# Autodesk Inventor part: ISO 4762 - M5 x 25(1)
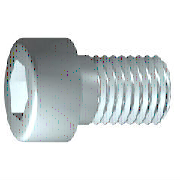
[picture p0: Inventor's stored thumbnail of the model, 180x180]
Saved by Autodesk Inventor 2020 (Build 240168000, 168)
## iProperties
Created: 2019-01
Part Number: ISO 4762 - M5 x 25(1)
Material: Nerezová ocel 440C
Description: Šroub s válcovou hlavou s vnitřním šestihranem
Document SubType Name: Modeling
Standard: ISO 4762
Designer: doma
Standard Revision: Fourth edition 2004-03-01
Standards Organization: ISO
Language: cs-CZ
Size Designation: M5 x 25
Categories: <MemberInstance><Categories><Category DisplayName="Spojovací materiál" InternalName="e4da775c-781d-43d5-af7c-5136215cf5a6" Mnemonic="FSTN"><Category DisplayName
Density: 7.75 g/cm^3
Appearance: Pololeštěná
IsCustomPart: 0
Author: doma
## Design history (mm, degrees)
sketch "Náčrt1"
  geometry: L1 (-1.167, 0)-(25, 0); L2 (25, 0)-(25, 2.5); L3 (25, 2.5)-(2, 2.5); L4 (2, 2.5)-(1.509, 2.5); L5 (1.509, 2.5)-(0, 2.5); L6 (0, 2.5)-(0, 4.25); L7 (0, 4.25)-(-5, 4.25); L8 (-5, 4.25)-(-5, 2.309); L9 (-5, 2.309)-(-2.5, 2.309); L10 (-2.5, 2.309)-(-1.167, 0); L11 (-11, 0)-(31, 0) reference; L12 (0, -0.85)-(0, 5.1) reference; L13 (2, 2.5)-(0, 2.5)
  constraints: 22 end point, 6 parallel, 2 collinear, 2 perpendicular, 1 horizontal, 1 point on line
  dimensions: "d1" = 23 distance from line of L3.end L2 (= GEL); "d2" = 0.49086 distance of L4.end L3.end (computed from GAL); "d3" = 5 distance between parallel lines of L8 L6 (= KOH); "d4" = 2.5 distance of L8.end L9.end (= INTI); "d5" = 60 deg angle of L10 L1; "d6" = 5 diameter of L3 L1 (= GD); "d7" = 5 diameter of L5 L1 (= BDM); "d8" = 4.6188 diameter of L9 L1 (= 1.1547 x SW); "d9" = 8.5 diameter of L7 L1 (= KOD); "d26" = 25 distance between parallel lines of L12 L2 (= NLG)
revolve "Těleso" sketch "Náčrt1" stored, may be unused: angle "d10" = 90 deg
sketch "Náčrt2"
  geometry: L1 (0, -5.95)-(0, 5.95) reference; L2 (-5.95, 0)-(5.95, 0) reference; L3 (2.309, 0)-(1.155, -2); L4 (1.155, -2)-(-1.155, -2); L5 (-1.155, -2)-(-2.309, 0); L6 (-2.309, 0)-(-1.155, 2); L7 (-1.155, 2)-(1.155, 2); L8 (1.155, 2)-(2.309, 0); 2 further points
  constraints: 12 end point, 1 coincident, 1 horizontal alignment, 1 point on line, 12 other
extrude "Drážka" join sketch "Náčrt2" stored distance "d11" = 10; taper "d12" = 0 deg
workplane "Work Plane1"
fillet "Fillet2" dims "d30" = 0.1 (= R)
body "Solid1"
fillet "Zaoblení1" dims "d17" = 0.5 (= RR)
feature "Závit" dims "d13" = 23 (= GEL), "d14" = 0
chamfer "Zkosení1" distance "d15" = 0.49076 (= -0.5 x SPD + 0.5 x GD); stored, may be unused: second distance "d16" = 0.49076 (= GUL), angle "d27" = 45 deg
other parameters: "GD" = 5 [user parameter; used in 2 equation terms], "NLG" = 25 [user parameter; used in 1 equation term], "GEL" = 23 [user parameter; used in 2 equation terms], "KOD" = 8.5 [user parameter; used in 1 equation term], "KOH" = 5 [user parameter; used in 1 equation term], "INTI" = 2.5 [user parameter; used in 1 equation term], "GAL" = 0.49076 (= 0.61345 x PTC) [user parameter; used in 1 equation term], "GUL" = 0.49076 (= 0.61345 x PTC) [user parameter; used in 1 equation term], "BDM" = 5 (= NND) [user parameter; used in 1 equation term], "SW" = 4 [user parameter; used in 2 equation terms], "RR" = 0.5 [user parameter; used in 1 equation term], "SPD" = 4.01848 (= NND - 1.2269 x PTC) [user parameter; used in 1 equation term], "d19" = 0, "d28" = 0, "d29" = 0, "R" = 0.1 [user parameter; used in 1 equation term], "TOA" = 30 deg [user parameter], "GD1" = 4.01848 (= THREADDIA - 1.2269 x PTC) [user parameter], "THREADDIA" = 5 [user parameter; used in 1 equation term], "FAWI" = 45 deg [user parameter], "TPU" = 12.5 (computed from PTC) [user parameter], "PTC" = 0.8 [user parameter; used in 5 equation terms], "NND" = 5 [user parameter; used in 2 equation terms], "E0" = 4.62 (= 1.155 x SW) [user parameter]
